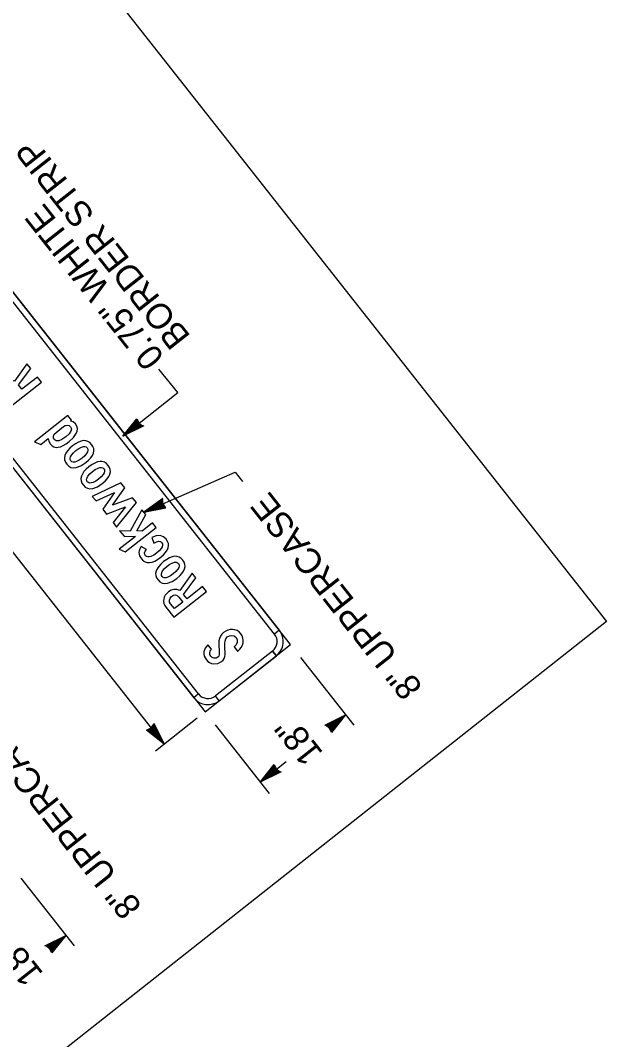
# Model space of a CAD drawing. Extents: x 671946 to 673995, y 1673066 to 1674936.
# Drawn here: x 672548.4 to 672645.4, y 1673764.1 to 1673932.5 of the extents above; entities that cross this region are included whole.
import ezdxf

# ---------------------------------------------------------------- set-up
doc = ezdxf.new("R2010")
doc.units = 0
doc.layers.add('C-ANNO-SYMB', color=7, linetype='Continuous')
doc.layers.add('Level 1', color=7, linetype='Continuous')

msp = doc.modelspace()

# ---------------------------------------------------------------- linework, layer by layer
at = {"layer": 'C-ANNO-SYMB'}
for p, q in [((672593.09, 1673829.37), (672515.08, 1673928.32)), ((672516.94, 1673925.96), (672591.23, 1673831.72)), ((672590.45, 1673831.11), (672516.16, 1673925.34)), ((672500.95, 1673917.17), (672578.96, 1673818.23)), ((672502.81, 1673914.82), (672577.1, 1673820.58)), ((672577.88, 1673821.2), (672503.59, 1673915.44)), ((672591.23, 1673831.72), (672590.45, 1673831.11)), ((672591.23, 1673831.72), (672590.45, 1673831.11)), ((672590.45, 1673831.11), (672590.45, 1673831.11)), ((672590.45, 1673831.11), (672590.45, 1673831.11)), ((672578.96, 1673818.23), (672593.09, 1673829.37)), ((672590.12, 1673828.3), (672580.69, 1673820.87)), ((672590.12, 1673828.3), (672590.74, 1673827.51)), ((672590.74, 1673827.51), (672590.12, 1673828.3)), ((672590.12, 1673828.3), (672590.74, 1673827.51)), ((672593.09, 1673829.37), (672593.09, 1673829.37)), ((672593.09, 1673829.37), (672593.09, 1673829.37)), ((672581.31, 1673820.08), (672590.74, 1673827.51)), ((672577.88, 1673821.2), (672577.1, 1673820.58)), ((672577.88, 1673821.2), (672577.1, 1673820.58)), ((672581.31, 1673820.08), (672580.69, 1673820.87)), ((672580.69, 1673820.87), (672580.69, 1673820.87)), ((672580.69, 1673820.87), (672580.69, 1673820.87)), ((672581.31, 1673820.08), (672580.69, 1673820.87))]:
    msp.add_line(p, q, dxfattribs=at)
for points in [[(672551.9, 1673872.75), (672551.23, 1673873.59), (672548.66, 1673871.57), (672548.1, 1673872.29), (672550.11, 1673875.02), (672549.5, 1673875.79), (672547.46, 1673872.91), (672547.01, 1673873.1), (672546.51, 1673873.12), (672546.05, 1673872.99), (672545.62, 1673872.73), (672545.31, 1673872.45), (672545.07, 1673872.16), (672544.91, 1673871.84), (672544.82, 1673871.51), (672544.8, 1673871.16), (672544.86, 1673870.8), (672545.01, 1673870.45), (672545.23, 1673870.11), (672546.51, 1673868.5), (672551.9, 1673872.75)], [(672556.86, 1673866.46), (672556.26, 1673867.22), (672550.76, 1673862.89), (672551.78, 1673862.45), (672553.03, 1673863.43), (672553.11, 1673862.98), (672553.39, 1673862.51), (672553.66, 1673862.24), (672553.96, 1673862.06), (672554.3, 1673861.97), (672554.67, 1673861.98), (672555.07, 1673862.08), (672555.51, 1673862.27), (672555.99, 1673862.55), (672556.5, 1673862.92), (672557.2, 1673863.57), (672557.65, 1673864.23), (672557.8, 1673864.66), (672557.83, 1673865.08), (672557.73, 1673865.48), (672557.5, 1673865.86), (672557.13, 1673866.17), (672556.67, 1673866.31), (672556.86, 1673866.46)], [(672555.56, 1673865.41), (672555.84, 1673865.57), (672556.15, 1673865.62), (672556.47, 1673865.56), (672556.71, 1673865.37), (672556.85, 1673865.02), (672556.76, 1673864.63), (672556.45, 1673864.18), (672555.9, 1673863.69), (672555.27, 1673863.25), (672554.74, 1673863.03), (672554.32, 1673863.02), (672554.01, 1673863.24), (672553.86, 1673863.53), (672553.86, 1673863.82), (672554.01, 1673864.12), (672554.31, 1673864.42), (672555.56, 1673865.41)], [(672557.02, 1673862.21), (672556.56, 1673861.81), (672556.19, 1673861.41), (672555.93, 1673861.02), (672555.76, 1673860.64), (672555.7, 1673860.26), (672555.73, 1673859.89), (672555.86, 1673859.53), (672556.09, 1673859.17), (672556.41, 1673858.86), (672556.77, 1673858.66), (672557.19, 1673858.58), (672557.65, 1673858.63), (672558.41, 1673858.91), (672559.21, 1673859.44), (672559.68, 1673859.84), (672560.05, 1673860.24), (672560.32, 1673860.63), (672560.49, 1673861.01), (672560.56, 1673861.38), (672560.53, 1673861.75), (672560.41, 1673862.1), (672560.18, 1673862.45), (672559.9, 1673862.75), (672559.58, 1673862.96), (672559.23, 1673863.07), (672558.85, 1673863.09), (672558.44, 1673863.01), (672558, 1673862.84), (672557.53, 1673862.57), (672557.02, 1673862.21)], [(672557.59, 1673861.43), (672558.07, 1673861.77), (672558.52, 1673862), (672558.83, 1673862.09), (672559.09, 1673862.1), (672559.3, 1673862.03), (672559.46, 1673861.89), (672559.57, 1673861.69), (672559.58, 1673861.47), (672559.51, 1673861.22), (672559.36, 1673860.95), (672559.04, 1673860.56), (672558.61, 1673860.18), (672558.14, 1673859.85), (672557.69, 1673859.63), (672557.39, 1673859.54), (672557.13, 1673859.54), (672556.92, 1673859.6), (672556.75, 1673859.75), (672556.65, 1673859.94), (672556.64, 1673860.16), (672556.71, 1673860.4), (672556.85, 1673860.67), (672557.17, 1673861.05), (672557.59, 1673861.43)], [(672559.75, 1673858.75), (672559.29, 1673858.35), (672558.92, 1673857.95), (672558.66, 1673857.56), (672558.49, 1673857.18), (672558.43, 1673856.8), (672558.46, 1673856.43), (672558.59, 1673856.07), (672558.82, 1673855.71), (672559.14, 1673855.39), (672559.51, 1673855.2), (672559.92, 1673855.12), (672560.38, 1673855.17), (672561.14, 1673855.45), (672561.94, 1673855.97), (672562.41, 1673856.38), (672562.78, 1673856.77), (672563.05, 1673857.16), (672563.22, 1673857.54), (672563.29, 1673857.92), (672563.26, 1673858.28), (672563.14, 1673858.64), (672562.91, 1673858.99), (672562.63, 1673859.29), (672562.31, 1673859.5), (672561.96, 1673859.61), (672561.58, 1673859.62), (672561.17, 1673859.55), (672560.73, 1673859.37), (672560.26, 1673859.11), (672559.75, 1673858.75)], [(672560.32, 1673857.97), (672560.8, 1673858.31), (672561.25, 1673858.53), (672561.56, 1673858.62), (672561.82, 1673858.63), (672562.03, 1673858.57), (672562.19, 1673858.42), (672562.3, 1673858.23), (672562.31, 1673858.01), (672562.25, 1673857.76), (672562.09, 1673857.48), (672561.77, 1673857.1), (672561.34, 1673856.72), (672560.87, 1673856.39), (672560.42, 1673856.17), (672560.12, 1673856.08), (672559.86, 1673856.07), (672559.65, 1673856.14), (672559.48, 1673856.28), (672559.39, 1673856.48), (672559.37, 1673856.7), (672559.44, 1673856.94), (672559.58, 1673857.21), (672559.9, 1673857.59), (672560.32, 1673857.97)], [(672572.1, 1673843.08), (672571.64, 1673842.68), (672571.28, 1673842.28), (672571.01, 1673841.89), (672570.84, 1673841.51), (672570.78, 1673841.13), (672570.81, 1673840.76), (672570.94, 1673840.4), (672571.17, 1673840.04), (672571.49, 1673839.73), (672571.86, 1673839.53), (672572.27, 1673839.45), (672572.73, 1673839.5), (672573.49, 1673839.78), (672574.29, 1673840.31), (672574.76, 1673840.71), (672575.13, 1673841.11), (672575.4, 1673841.5), (672575.57, 1673841.88), (672575.64, 1673842.25), (672575.62, 1673842.62), (672575.49, 1673842.97), (672575.26, 1673843.32), (672574.98, 1673843.62), (672574.66, 1673843.83), (672574.31, 1673843.94), (672573.93, 1673843.96), (672573.52, 1673843.88), (672573.08, 1673843.71), (672572.61, 1673843.44), (672572.1, 1673843.08)], [(672572.67, 1673842.3), (672573.15, 1673842.64), (672573.6, 1673842.87), (672573.91, 1673842.96), (672574.17, 1673842.97), (672574.38, 1673842.9), (672574.55, 1673842.76), (672574.65, 1673842.56), (672574.66, 1673842.34), (672574.6, 1673842.09), (672574.44, 1673841.82), (672574.12, 1673841.43), (672573.69, 1673841.05), (672573.22, 1673840.72), (672572.77, 1673840.5), (672572.47, 1673840.41), (672572.21, 1673840.41), (672572, 1673840.47), (672571.83, 1673840.62), (672571.74, 1673840.81), (672571.72, 1673841.03), (672571.79, 1673841.27), (672571.93, 1673841.54), (672572.25, 1673841.92), (672572.67, 1673842.3)], [(672579.2, 1673838.12), (672578.53, 1673838.96), (672575.97, 1673836.94), (672575.4, 1673837.66), (672577.41, 1673840.39), (672576.8, 1673841.16), (672574.76, 1673838.28), (672574.31, 1673838.47), (672573.81, 1673838.49), (672573.35, 1673838.36), (672572.92, 1673838.1), (672572.61, 1673837.82), (672572.38, 1673837.52), (672572.21, 1673837.21), (672572.12, 1673836.88), (672572.1, 1673836.52), (672572.16, 1673836.17), (672572.31, 1673835.82), (672572.54, 1673835.48), (672573.81, 1673833.87), (672579.2, 1673838.12)], [(672575.26, 1673836.38), (672573.88, 1673835.3), (672573.26, 1673836.09), (672573.09, 1673836.4), (672573.05, 1673836.73), (672573.16, 1673837.05), (672573.41, 1673837.32), (672573.74, 1673837.51), (672574.05, 1673837.56), (672574.34, 1673837.45), (672574.61, 1673837.2), (672575.26, 1673836.38)]]:
    msp.add_lwpolyline(points, dxfattribs=at)
for points in [[(672564.3, 1673848.75), (672567.6, 1673852.83), (672566.97, 1673853.63), (672563.66, 1673852.39), (672565.66, 1673855.29), (672565.01, 1673856.11), (672560.28, 1673853.86), (672560.94, 1673853.11), (672563.96, 1673854.5), (672562.03, 1673851.74), (672562.67, 1673850.92), (672565.81, 1673852.13), (672563.75, 1673849.55)], [(672570.84, 1673848.73), (672570.25, 1673849.47), (672568.53, 1673848.11), (672567.67, 1673848.14), (672569.16, 1673850.85), (672568.52, 1673851.66), (672566.57, 1673848.13), (672564.79, 1673848.14), (672565.55, 1673847.27), (672567.43, 1673847.24), (672564.76, 1673845.13), (672565.75, 1673844.72)], [(672570.5, 1673846.15), (672570.93, 1673846.36), (672571.29, 1673846.44), (672571.58, 1673846.38), (672571.81, 1673846.21), (672571.91, 1673846.01), (672571.92, 1673845.79), (672571.85, 1673845.54), (672571.69, 1673845.27), (672571.37, 1673844.88), (672570.94, 1673844.5), (672570.47, 1673844.17), (672570.01, 1673843.95), (672569.71, 1673843.86), (672569.46, 1673843.85), (672569.25, 1673843.92), (672569.08, 1673844.06), (672568.97, 1673844.28), (672568.96, 1673844.52), (672569.05, 1673844.79), (672569.25, 1673845.07), (672568.37, 1673845.57), (672568.1, 1673845.08), (672568.02, 1673844.56), (672568.13, 1673844.03), (672568.42, 1673843.53), (672568.71, 1673843.23), (672569.03, 1673843.03), (672569.38, 1673842.92), (672569.76, 1673842.91), (672570.18, 1673842.99), (672570.62, 1673843.17), (672571.1, 1673843.44), (672571.61, 1673843.81), (672572.07, 1673844.2), (672572.43, 1673844.59), (672572.69, 1673844.97), (672572.85, 1673845.35), (672572.92, 1673845.72), (672572.89, 1673846.08), (672572.76, 1673846.43), (672572.54, 1673846.78), (672572.08, 1673847.19), (672571.53, 1673847.38), (672570.89, 1673847.34), (672570.15, 1673847.07)], [(672584.34, 1673828.26), (672584.39, 1673828.3), (672584.7, 1673828.58), (672584.94, 1673828.9), (672585.12, 1673829.25), (672585.23, 1673829.64), (672585.27, 1673830.05), (672585.22, 1673830.44), (672585.08, 1673830.8), (672584.86, 1673831.15), (672584.58, 1673831.45), (672584.25, 1673831.67), (672583.9, 1673831.81), (672583.5, 1673831.87), (672583.1, 1673831.85), (672582.73, 1673831.76), (672582.37, 1673831.6), (672582.02, 1673831.37), (672581.73, 1673831.09), (672581.51, 1673830.77), (672581.34, 1673830.39), (672581.24, 1673829.97), (672581.22, 1673829.29), (672581.28, 1673828.33), (672581.29, 1673827.67), (672581.21, 1673827.46), (672581.05, 1673827.28), (672580.77, 1673827.14), (672580.46, 1673827.13), (672580.15, 1673827.23), (672579.91, 1673827.44), (672579.74, 1673827.74), (672579.72, 1673828.04), (672579.82, 1673828.29), (672580.03, 1673828.58), (672579.43, 1673829.33), (672578.98, 1673828.78), (672578.77, 1673828.15), (672578.77, 1673827.81), (672578.83, 1673827.47), (672578.97, 1673827.15), (672579.18, 1673826.83), (672579.42, 1673826.58), (672579.7, 1673826.39), (672580.02, 1673826.26), (672580.37, 1673826.19), (672581.06, 1673826.24), (672581.66, 1673826.55), (672581.92, 1673826.79), (672582.1, 1673827.06), (672582.23, 1673827.37), (672582.3, 1673827.72), (672582.23, 1673829.09), (672582.22, 1673829.61), (672582.25, 1673829.95), (672582.38, 1673830.34), (672582.61, 1673830.63), (672582.98, 1673830.83), (672583.37, 1673830.89), (672583.77, 1673830.79), (672584.08, 1673830.53), (672584.27, 1673830.14), (672584.25, 1673829.71), (672584.07, 1673829.33), (672583.75, 1673829.01)]]:
    msp.add_lwpolyline(points, close=True, dxfattribs=at)
for centre, radius, start, end in [((672588.88, 1673829.87), 3, 308.2504, 38.2506), ((672588.88, 1673829.87), 2, 308.2504, 38.2506), ((672579.45, 1673822.44), 2, 218.2508, 308.2504), ((672579.45, 1673822.44), 3, 218.2508, 308.2504)]:
    msp.add_arc(centre, radius, start, end, dxfattribs=at)
at = {"layer": 'Level 1'}
for p, q in [((672505.58, 1674010.48), (672645.37, 1673833.17)), ((672565.34, 1673863.79), (672567.66, 1673866.7)), ((672567.66, 1673866.7), (672568.05, 1673865.94)), ((672568.8, 1673865.5), (672565.34, 1673863.79)), ((672565.56, 1673864.03), (672567.64, 1673866.55)), ((672568.44, 1673865.48), (672565.6, 1673864.06)), ((672568.61, 1673865.45), (672565.76, 1673864.15)), ((672565.91, 1673864.3), (672567.64, 1673866.39)), ((672566.13, 1673864.4), (672567.68, 1673866.12)), ((672568.32, 1673865.56), (672566.13, 1673864.4)), ((672566.2, 1673864.53), (672567.64, 1673866.25)), ((672568.32, 1673865.56), (672566.2, 1673864.53)), ((672566.63, 1673864.87), (672567.62, 1673865.98)), ((672568.14, 1673865.61), (672566.63, 1673864.87)), ((672567.18, 1673865.23), (672566.92, 1673865.13)), ((672567.02, 1673865.14), (672567.59, 1673865.85)), ((672567.98, 1673865.65), (672567.02, 1673865.14)), ((672567.68, 1673865.99), (672567.18, 1673865.23)), ((672567.35, 1673865.43), (672567.62, 1673865.77)), ((672567.87, 1673865.7), (672567.35, 1673865.43)), ((672567.59, 1673865.85), (672567.87, 1673865.7)), ((672567.62, 1673865.98), (672567.98, 1673865.65)), ((672567.62, 1673865.77), (672567.7, 1673865.71)), ((672567.64, 1673866.55), (672567.98, 1673865.99)), ((672567.64, 1673866.39), (672567.78, 1673866.13)), ((672567.64, 1673866.25), (672568.32, 1673865.56)), ((672567.68, 1673866.12), (672568.14, 1673865.61)), ((672568.06, 1673865.72), (672567.68, 1673865.99)), ((672567.7, 1673865.71), (672568.06, 1673865.72)), ((672567.78, 1673866.13), (672568.32, 1673865.56)), ((672567.98, 1673865.99), (672568.65, 1673865.52)), ((672568.05, 1673865.94), (672568.29, 1673865.63)), ((672568.29, 1673865.63), (672568.61, 1673865.45)), ((672568.65, 1673865.52), (672568.43, 1673865.58)), ((672568.43, 1673865.58), (672568.44, 1673865.48)), ((672572.2, 1673812.9), (672539.32, 1673854.61)), ((672571.96, 1673853.52), (672568.84, 1673851.25)), ((672571.78, 1673853.21), (672569.2, 1673851.36)), ((672571.82, 1673853.37), (672569.35, 1673851.46)), ((672571.86, 1673853.16), (672571.78, 1673853.21)), ((672571.84, 1673853.01), (672571.82, 1673853.37)), ((672571.9, 1673853.38), (672571.86, 1673853.16)), ((672572.01, 1673852.57), (672571.9, 1673853.38)), ((672568.84, 1673851.25), (672572.49, 1673851.95)), ((672569.15, 1673851.33), (672572.35, 1673852)), ((672569.2, 1673851.36), (672569.32, 1673851.53)), ((672569.32, 1673851.53), (672570.07, 1673852.03)), ((672569.56, 1673851.52), (672572.2, 1673852.08)), ((672570.07, 1673852.03), (672569.56, 1673851.52)), ((672571.79, 1673853.07), (672569.75, 1673851.66)), ((672569.75, 1673851.66), (672571.99, 1673852.24)), ((672571.79, 1673853.07), (672569.89, 1673851.67)), ((672569.89, 1673851.67), (672572.09, 1673852.14)), ((672570.28, 1673851.87), (672570.67, 1673852.16)), ((672570.76, 1673852.03), (672570.28, 1673851.87)), ((672571.75, 1673852.88), (672570.39, 1673851.89)), ((672570.39, 1673851.89), (672571.83, 1673852.26)), ((672570.97, 1673852.21), (672570.76, 1673852.03)), ((672571.71, 1673852.72), (672570.81, 1673852.11)), ((672570.81, 1673852.11), (672571.71, 1673852.29)), ((672571.87, 1673852.3), (672570.97, 1673852.21)), ((672571.71, 1673852.6), (672571.23, 1673852.27)), ((672571.23, 1673852.27), (672571.65, 1673852.35)), ((672571.63, 1673852.45), (672571.81, 1673852.76)), ((672571.65, 1673852.35), (672571.63, 1673852.45)), ((672571.83, 1673852.26), (672571.71, 1673852.72)), ((672571.71, 1673852.29), (672571.71, 1673852.6)), ((672571.99, 1673852.24), (672571.75, 1673852.88)), ((672572.04, 1673852.32), (672571.79, 1673853.07)), ((672572.09, 1673852.14), (672571.79, 1673853.07)), ((672571.81, 1673852.76), (672571.87, 1673852.3)), ((672572, 1673852.65), (672571.84, 1673853.01)), ((672572.49, 1673851.95), (672572, 1673852.65)), ((672572.35, 1673852), (672572.01, 1673852.57)), ((672572.2, 1673852.08), (672572.04, 1673852.32)), ((672569.35, 1673851.46), (672569.15, 1673851.33)), ((672645.37, 1673833.17), (672451.3, 1673680.17)), ((672594.74, 1673827.22), (672603.57, 1673816.02)), ((672570, 1673815.54), (672570.48, 1673816.21)), ((672570.36, 1673815.85), (672570.55, 1673816.17)), ((672570.48, 1673816.21), (672570.41, 1673815.99)), ((672570.5, 1673816.36), (672572.2, 1673812.9)), ((672570.55, 1673816.17), (672571.84, 1673813.32)), ((672577.66, 1673817.2), (672570.75, 1673811.76)), ((672598.74, 1673816.05), (672602.2, 1673817.76)), ((672598.93, 1673816.11), (672601.78, 1673817.4)), ((672599.24, 1673815.92), (672598.93, 1673816.11)), ((672599.1, 1673816.07), (672601.94, 1673817.49)), ((672599.22, 1673815.99), (672601.41, 1673817.15)), ((672599.22, 1673815.99), (672601.34, 1673817.02)), ((672599.4, 1673815.94), (672600.91, 1673816.68)), ((672599.56, 1673815.9), (672600.52, 1673816.41)), ((672599.67, 1673815.85), (672600.18, 1673816.12)), ((672599.85, 1673815.56), (672600.36, 1673816.32)), ((672601.41, 1673817.15), (672599.86, 1673815.43)), ((672602.2, 1673817.76), (672599.88, 1673814.85)), ((672601.98, 1673817.52), (672599.9, 1673815)), ((672601.63, 1673817.24), (672599.9, 1673815.16)), ((672601.34, 1673817.02), (672599.9, 1673815.3)), ((672600.91, 1673816.68), (672599.91, 1673815.57)), ((672600.18, 1673816.12), (672599.92, 1673815.78)), ((672600.52, 1673816.41), (672599.95, 1673815.7)), ((672600.36, 1673816.32), (672600.61, 1673816.42)), ((672600.97, 1673816.77), (672600.54, 1673816.56)), ((672600.61, 1673816.42), (672600.97, 1673816.77)), ((672601.73, 1673817.46), (672600.93, 1673817.03)), ((672600.93, 1673817.03), (672601.63, 1673817.24)), ((672601.94, 1673817.49), (672601.73, 1673817.46)), ((672601.78, 1673817.4), (672601.98, 1673817.52)), ((672569.29, 1673815.22), (672570.05, 1673815.61)), ((672572.2, 1673812.9), (672569.29, 1673815.22)), ((672569.44, 1673815.2), (672570, 1673815.54)), ((672571.96, 1673813.12), (672569.44, 1673815.2)), ((672569.61, 1673815.2), (672569.87, 1673815.34)), ((672571.69, 1673813.47), (672569.61, 1673815.2)), ((672569.74, 1673815.2), (672570.44, 1673815.88)), ((672571.46, 1673813.76), (672569.74, 1673815.2)), ((672569.87, 1673815.34), (672570.44, 1673815.88)), ((672569.87, 1673815.24), (672570.38, 1673815.7)), ((672571.59, 1673813.69), (672569.87, 1673815.24)), ((672570.28, 1673815.62), (672570, 1673815.24)), ((672570, 1673815.24), (672570.76, 1673814.74)), ((672570.02, 1673815.19), (672570.34, 1673815.54)), ((672571.12, 1673814.19), (672570.02, 1673815.19)), ((672570.05, 1673815.61), (672570.36, 1673815.85)), ((672570.14, 1673815.15), (672570.29, 1673815.43)), ((672570.86, 1673814.58), (672570.14, 1673815.15)), ((672570.22, 1673815.18), (672570.29, 1673815.26)), ((672570.56, 1673814.91), (672570.22, 1673815.18)), ((672570.29, 1673815.26), (672570.28, 1673815.62)), ((672570.29, 1673815.43), (672570.56, 1673814.91)), ((672570.34, 1673815.54), (672570.86, 1673814.58)), ((672570.38, 1673815.7), (672571.12, 1673814.19)), ((672570.41, 1673815.99), (672570.51, 1673816)), ((672570.44, 1673815.88), (672571.46, 1673813.76)), ((672570.44, 1673815.88), (672571.59, 1673813.69)), ((672570.51, 1673816), (672571.93, 1673813.16)), ((672570.76, 1673814.74), (672570.86, 1673814.49)), ((672570.86, 1673814.49), (672571.21, 1673814.12)), ((672571.21, 1673814.12), (672571, 1673814.56)), ((672580.6, 1673816.08), (672589.56, 1673804.72)), ((672599.55, 1673815.56), (672598.88, 1673816.03)), ((672598.88, 1673816.03), (672599.1, 1673815.97)), ((672599.1, 1673815.97), (672599.1, 1673816.07)), ((672599.76, 1673815.42), (672599.22, 1673815.99)), ((672599.9, 1673815.3), (672599.22, 1673815.99)), ((672599.49, 1673815.61), (672599.24, 1673815.92)), ((672599.86, 1673815.43), (672599.4, 1673815.94)), ((672599.83, 1673815.84), (672599.48, 1673815.83)), ((672599.48, 1673815.83), (672599.85, 1673815.56)), ((672599.88, 1673814.85), (672599.49, 1673815.61)), ((672599.9, 1673815), (672599.55, 1673815.56)), ((672599.91, 1673815.57), (672599.56, 1673815.9)), ((672599.95, 1673815.7), (672599.67, 1673815.85)), ((672599.9, 1673815.16), (672599.76, 1673815.42)), ((672599.92, 1673815.78), (672599.83, 1673815.84)), ((672571.9, 1673813.37), (672571.48, 1673814.17)), ((672571.48, 1673814.17), (672571.69, 1673813.47)), ((672571.84, 1673813.32), (672571.96, 1673813.12)), ((672571.93, 1673813.16), (672571.9, 1673813.37)), ((672588.06, 1673806.61), (672592.39, 1673810.02)), ((672588.06, 1673806.61), (672590.38, 1673809.52)), ((672588.28, 1673806.85), (672590.37, 1673809.37)), ((672590.37, 1673809.37), (672590.71, 1673808.81)), ((672590.38, 1673809.52), (672590.78, 1673808.76)), ((672591.52, 1673808.32), (672588.06, 1673806.61)), ((672591.17, 1673808.3), (672588.32, 1673806.88)), ((672591.33, 1673808.26), (672588.48, 1673806.97)), ((672588.63, 1673807.12), (672590.36, 1673809.2)), ((672588.85, 1673807.22), (672590.41, 1673808.94)), ((672591.05, 1673808.37), (672588.85, 1673807.22)), ((672588.92, 1673807.35), (672590.37, 1673809.07)), ((672591.05, 1673808.37), (672588.92, 1673807.35)), ((672589.65, 1673807.95), (672589.29, 1673807.6)), ((672589.29, 1673807.6), (672589.72, 1673807.81)), ((672589.36, 1673807.69), (672590.35, 1673808.79)), ((672590.87, 1673808.43), (672589.36, 1673807.69)), ((672589.9, 1673808.05), (672589.65, 1673807.95)), ((672589.74, 1673807.96), (672590.32, 1673808.67)), ((672590.7, 1673808.47), (672589.74, 1673807.96)), ((672590.41, 1673808.81), (672589.9, 1673808.05)), ((672590.08, 1673808.25), (672590.35, 1673808.59)), ((672590.6, 1673808.52), (672590.08, 1673808.25)), ((672590.32, 1673808.67), (672590.6, 1673808.52)), ((672590.35, 1673808.79), (672590.7, 1673808.47)), ((672590.35, 1673808.59), (672590.43, 1673808.53)), ((672590.36, 1673809.2), (672590.5, 1673808.94)), ((672590.37, 1673809.07), (672591.05, 1673808.37)), ((672590.41, 1673808.94), (672590.87, 1673808.43)), ((672590.79, 1673808.54), (672590.41, 1673808.81)), ((672590.43, 1673808.53), (672590.79, 1673808.54)), ((672590.5, 1673808.94), (672591.05, 1673808.37)), ((672590.71, 1673808.81), (672591.38, 1673808.33)), ((672590.78, 1673808.76), (672591.02, 1673808.45)), ((672591.02, 1673808.45), (672591.33, 1673808.26)), ((672591.38, 1673808.33), (672591.16, 1673808.4)), ((672591.16, 1673808.4), (672591.17, 1673808.3)), ((672588.48, 1673806.97), (672588.28, 1673806.85)), ((672588.32, 1673806.88), (672588.53, 1673806.91)), ((672588.53, 1673806.91), (672589.33, 1673807.33)), ((672589.33, 1673807.33), (672588.63, 1673807.12)), ((672548.47, 1673790.75), (672557.3, 1673779.55)), ((672552.47, 1673779.58), (672555.94, 1673781.28)), ((672552.67, 1673779.63), (672555.51, 1673780.92)), ((672552.83, 1673779.59), (672555.68, 1673781.02)), ((672555.94, 1673781.28), (672553.61, 1673778.38)), ((672555.72, 1673781.05), (672553.63, 1673778.52)), ((672555.37, 1673780.77), (672553.63, 1673778.69)), ((672555.47, 1673780.99), (672554.67, 1673780.56)), ((672554.67, 1673780.56), (672555.37, 1673780.77)), ((672555.68, 1673781.02), (672555.47, 1673780.99)), ((672555.51, 1673780.92), (672555.72, 1673781.05)), ((672553.29, 1673779.09), (672552.62, 1673779.56)), ((672552.62, 1673779.56), (672552.84, 1673779.5)), ((672552.98, 1673779.45), (672552.67, 1673779.63)), ((672552.84, 1673779.5), (672552.83, 1673779.59)), ((672552.95, 1673779.52), (672555.15, 1673780.67)), ((672552.95, 1673779.52), (672555.08, 1673780.55)), ((672553.5, 1673778.95), (672552.95, 1673779.52)), ((672553.63, 1673778.82), (672552.95, 1673779.52)), ((672553.22, 1673779.14), (672552.98, 1673779.45)), ((672553.13, 1673779.46), (672554.64, 1673780.21)), ((672553.59, 1673778.96), (672553.13, 1673779.46)), ((672553.57, 1673779.37), (672553.21, 1673779.36)), ((672553.21, 1673779.36), (672553.59, 1673779.09)), ((672553.61, 1673778.38), (672553.22, 1673779.14)), ((672553.29, 1673779.42), (672554.25, 1673779.94)), ((672553.65, 1673779.1), (672553.29, 1673779.42)), ((672553.63, 1673778.52), (672553.29, 1673779.09)), ((672553.4, 1673779.38), (672553.92, 1673779.65)), ((672553.68, 1673779.23), (672553.4, 1673779.38)), ((672553.65, 1673779.31), (672553.57, 1673779.37)), ((672555.15, 1673780.67), (672553.59, 1673778.96)), ((672553.59, 1673779.09), (672554.1, 1673779.85)), ((672555.08, 1673780.55), (672553.63, 1673778.82)), ((672554.64, 1673780.21), (672553.65, 1673779.1)), ((672553.92, 1673779.65), (672553.65, 1673779.31)), ((672554.25, 1673779.94), (672553.68, 1673779.23)), ((672554.1, 1673779.85), (672554.35, 1673779.95)), ((672554.71, 1673780.3), (672554.27, 1673780.09)), ((672554.35, 1673779.95), (672554.71, 1673780.3)), ((672553.63, 1673778.69), (672553.5, 1673778.95))]:
    msp.add_line(p, q, dxfattribs=at)
for points in [[(672565.34, 1673863.79), (672574.45, 1673871.05), (672571.31, 1673874.91)], [(672568.84, 1673851.25), (672583.95, 1673857.89), (672585.17, 1673856.34)]]:
    msp.add_lwpolyline(points, dxfattribs=at)

# ---------------------------------------------------------------- texts
for s, p in [('BORDER STRIP', (672576.68, 1673880.31)), ('0.75" WHITE ', (672572.38, 1673876.92)), ('8" UPPERCASE', (672615.09, 1673822.39)), ('8" UPPERCASE', (672568.66, 1673786.13)), ('18"', (672598.61, 1673811.45)), ('18"', (672552.34, 1673774.98))]:
    msp.add_text(s, height=4.2, rotation=128.2505, dxfattribs=at).set_placement(p)

doc.saveas('drawing.dxf')
